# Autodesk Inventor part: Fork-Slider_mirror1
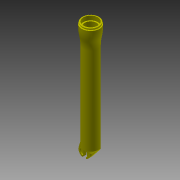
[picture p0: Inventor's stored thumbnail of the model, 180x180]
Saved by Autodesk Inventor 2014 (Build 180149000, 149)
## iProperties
Shininess: 64.0
Length Units: 11272
Angle Units: 11279
Time Units: 11290
Mass Units: 11286
Length Display Precision: 3
Angle Display Precision: 2
Compacted: True
Part Number: Fork-Slider_mirror1
Document SubType Name: Modeling
Created: 2003-10
Designer: Autodesk, Inc.
Material: Generic
Manufacturer: Standard
Standards Organization: Custom
Mass: 115.052 g
Surface Area: 625.893 cm^2
Volume: 115.052 cm^3
Density: 1 g/cm^3
Appearance: Yellow (Flat)
Density: 0.0
Volumn: 0.0
Area: 0.0
PropertySet Name: Model Information
Control State: 0
Master: False
Checked Out: False
Author: Autodesk, Inc.
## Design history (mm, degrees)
derived "Fork-Slider.ipt"
  workplane "Work Plane3"
  node "WorkPlane4"
  workplane "Work Plane8"
  node "WorkPlane5"
  node "WorkPlane1"
  node "WorkPlane2"
  node "WorkPlane3"
  node "WorkAxis1"
body "Solid1"
tag "TaggingFeature2"
workplane "Work Plane10"
workplane "Work Plane11"
workplane "Work Plane5"
workplane "Work Plane6"
feature "DerivedBody::Fork-Slider.ipt"
